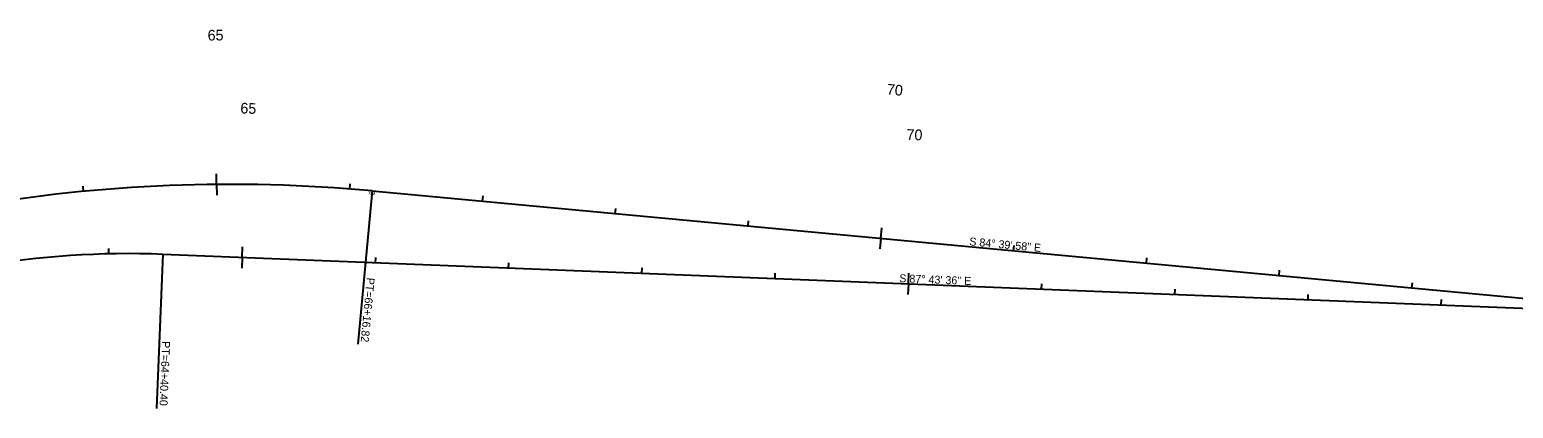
# Model space of a CAD drawing. Extents: x 1965771 to 1970246, y 1117124 to 1118239.
# Drawn here: x 1968020 to 1969133, y 1117815 to 1118099 of the extents above; entities that cross this region are included whole.
import ezdxf

# ---------------------------------------------------------------- set-up
doc = ezdxf.new("R2010")
doc.units = 0
for name, color, linetype in [('RD_HC_Cl', 7, 'Continuous'), ('RD_HC_Data', 7, 'Continuous'), ('RD_HC_Data_Tic', 7, 'Continuous'), ('RD_HC_Points', 7, 'Continuous'), ('RD_HC_TX_Sta50', 7, 'Continuous')]:
    doc.layers.add(name, color=color, linetype=linetype)

msp = doc.modelspace()

# ---------------------------------------------------------------- linework, layer by layer
at = {"layer": 'RD_HC_Cl'}
for p, q in [((1968277.4, 1117978.5), (1969226.4, 1117889.9)), ((1968120.3, 1117930.9), (1969279, 1117884.9))]:
    msp.add_line(p, q, dxfattribs=at)
for centre, radius, start, end in [((1968170.8, 1116837.5), 1145.9, 84.6661, 115.0463), ((1968094.4, 1117277.5), 653.9, 87.7266, 111.9958)]:
    msp.add_arc(centre, radius, start, end, dxfattribs=at)
at = {"layer": 'RD_HC_Data'}
for p, q in [((1968277.4, 1117978.5), (1968266.6, 1117863.4)), ((1968120.3, 1117930.9), (1968115.7, 1117815.3))]:
    msp.add_line(p, q, dxfattribs=at)
at = {"layer": 'RD_HC_Data_Tic'}
for p, q in [((1968160.7, 1117983.4), (1968160.6, 1117991.4)), ((1968060.9, 1117978.1), (1968060.5, 1117982.1)), ((1968160.7, 1117983.4), (1968160.8, 1117975.4)), ((1968260.6, 1117979.9), (1968260.9, 1117983.9)), ((1968360.2, 1117970.7), (1968360.5, 1117974.7)), ((1968459.7, 1117961.4), (1968460.1, 1117965.4)), ((1968559.3, 1117952.1), (1968559.7, 1117956.1)), ((1968658.9, 1117942.8), (1968658.1, 1117934.9)), ((1968658.9, 1117942.8), (1968659.6, 1117950.8)), ((1968079.9, 1117931.3), (1968079.8, 1117935.3)), ((1968179.9, 1117928.6), (1968180.2, 1117936.6)), ((1968758.4, 1117933.5), (1968758.8, 1117937.5)), ((1968179.9, 1117928.6), (1968179.6, 1117920.6)), ((1968279.8, 1117924.6), (1968280, 1117928.6)), ((1968379.7, 1117920.6), (1968379.9, 1117924.6)), ((1968479.6, 1117916.7), (1968479.8, 1117920.7)), ((1968858, 1117924.3), (1968858.4, 1117928.2)), ((1968579.6, 1117912.7), (1968579.7, 1117916.7)), ((1968679.5, 1117908.7), (1968679.2, 1117900.8)), ((1968679.5, 1117908.7), (1968679.8, 1117916.7)), ((1968779.4, 1117904.8), (1968779.6, 1117908.8)), ((1968957.6, 1117915), (1968957.9, 1117918.9)), ((1969057.1, 1117905.7), (1969057.5, 1117909.6)), ((1968879.3, 1117900.8), (1968879.5, 1117904.8)), ((1968979.3, 1117896.8), (1968979.4, 1117900.8)), ((1969079.2, 1117892.9), (1969079.3, 1117896.9))]:
    msp.add_line(p, q, dxfattribs=at)

# ---------------------------------------------------------------- texts
at = {"layer": 'RD_HC_Data'}
for s, rotation, p in [('S 84%%d 39\' 58" E', 354.6661, (1968725, 1117937.7)), ('PT=66+16.82', 264.6661, (1968273.3, 1117913.6)), ('S 87%%d 43\' 36" E', 357.7266, (1968672.6, 1117910)), ('PT=64+40.40', 267.7266, (1968119.8, 1117865.9))]:
    msp.add_text(s, height=6, rotation=rotation, dxfattribs=at).set_placement(p)
at = {"layer": 'RD_HC_Points'}
msp.add_text('69', height=3, dxfattribs=at).set_placement((1968275.1, 1117975.5))
at = {"layer": 'RD_HC_TX_Sta50'}
for s, rotation, p in [('65', 0.5072, (1968154, 1118091.3)), ('70', 354.6661, (1968663.1, 1118050.9)), ('65', 357.7266, (1968178.4, 1118036.7)), ('70', 357.7266, (1968678, 1118016.9))]:
    msp.add_text(s, height=8, rotation=rotation, dxfattribs=at).set_placement(p)

doc.saveas('drawing.dxf')
